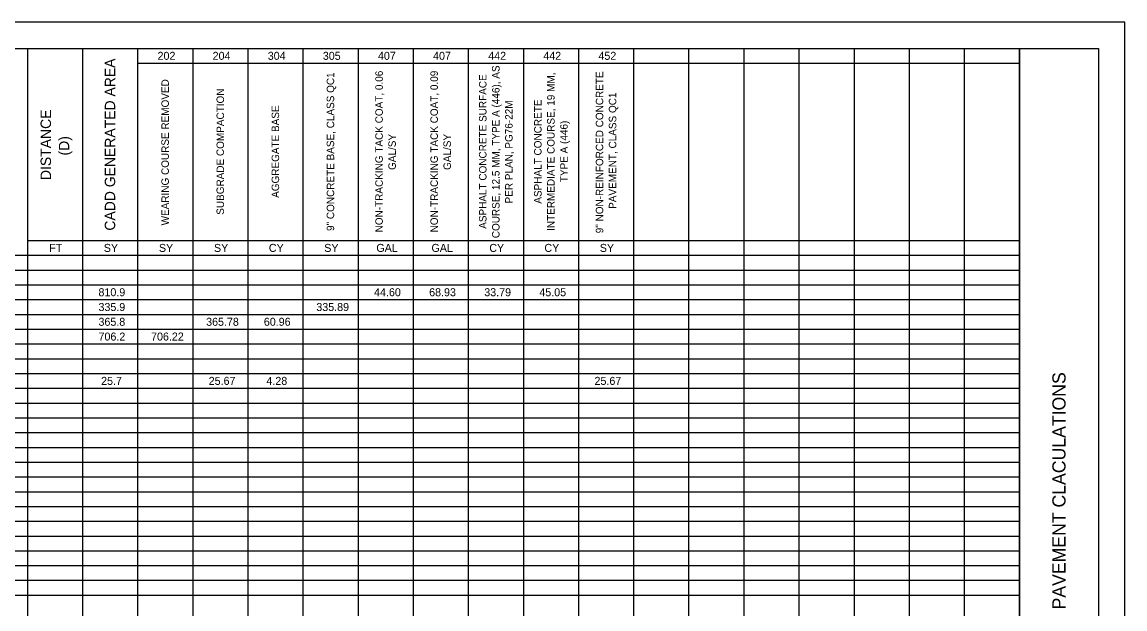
# Model space of a CAD drawing. Extents: x 0 to 34, y 0 to 22.
# Drawn here: x 13.11 to 34, y 10.88 to 22 of the extents above; entities that cross this region are included whole.
import ezdxf

# ---------------------------------------------------------------- set-up
doc = ezdxf.new("R2010")
doc.units = 0
for name, color, linetype in [('SH_Border', 7, 'Continuous'), ('SH_Cut_Line', 7, 'Continuous'), ('SH_Data', 7, 'Continuous'), ('SH_Text', 7, 'Continuous')]:
    doc.layers.add(name, color=color, linetype=linetype)

msp = doc.modelspace()

# ---------------------------------------------------------------- linework, layer by layer
at = {"layer": 'SH_Border'}
msp.add_line((32, 0.5), (32, 21.5), dxfattribs=at)
msp.add_lwpolyline([(1.5, 21.5), (33.5, 21.5), (33.5, 0.5), (1.5, 0.5)], close=True, dxfattribs=at)
at = {"layer": 'SH_Cut_Line'}
msp.add_lwpolyline([(0, 0), (34, 0), (34, 22), (0, 22)], close=True, dxfattribs=at)
at = {"layer": 'SH_Text'}
for p, q in [((1.5, 21.5), (32, 21.5)), ((13.212, 21.5), (13.212, 1.34)), ((14.256, 21.5), (14.256, 1.34)), ((15.299, 21.5), (15.299, 0.5)), ((16.343, 21.5), (16.343, 0.5)), ((17.387, 21.5), (17.387, 0.5)), ((18.431, 21.5), (18.431, 0.5)), ((19.475, 21.5), (19.475, 0.5)), ((20.518, 21.5), (20.518, 0.78)), ((21.562, 21.5), (21.562, 0.5)), ((22.606, 21.5), (22.606, 0.5)), ((23.65, 21.5), (23.65, 0.5)), ((24.694, 21.5), (24.694, 0.5)), ((25.737, 21.5), (25.737, 0.5)), ((26.781, 21.5), (26.781, 0.5)), ((27.825, 21.5), (27.825, 0.5)), ((28.869, 21.5), (28.869, 0.5)), ((29.912, 21.5), (29.912, 0.5)), ((30.956, 21.5), (30.956, 0.5)), ((32, 21.5), (32, 0.5)), ((15.299, 21.22), (32, 21.22)), ((13.212, 17.86), (32, 17.86)), ((1.5, 17.58), (32, 17.58)), ((1.5, 17.3), (32, 17.3)), ((1.5, 17.02), (32, 17.02)), ((1.5, 16.74), (32, 16.74)), ((1.5, 16.46), (32, 16.46)), ((1.5, 16.18), (32, 16.18)), ((1.5, 15.9), (32, 15.9)), ((1.5, 15.62), (32, 15.62)), ((1.5, 15.34), (32, 15.34)), ((1.5, 15.06), (32, 15.06)), ((1.5, 14.78), (32, 14.78)), ((1.5, 14.5), (32, 14.5)), ((1.5, 14.22), (32, 14.22)), ((1.5, 13.94), (32, 13.94)), ((1.5, 13.66), (32, 13.66)), ((1.5, 13.38), (32, 13.38)), ((1.5, 13.1), (32, 13.1)), ((1.5, 12.82), (32, 12.82)), ((1.5, 12.54), (32, 12.54)), ((1.5, 12.26), (32, 12.26)), ((1.5, 11.98), (32, 11.98)), ((1.5, 11.7), (32, 11.7)), ((1.5, 11.42), (32, 11.42)), ((1.5, 11.14), (32, 11.14))]:
    msp.add_line(p, q, dxfattribs=at)

# ---------------------------------------------------------------- texts
at = {"layer": 'SH_Data'}
msp.add_text('PAVEMENT CLACULATIONS', height=0.25, rotation=90, dxfattribs=at).set_placement((32.875, 10.868))
at = {"layer": 'SH_Text'}
for s, height, p in [('CADD GENERATED AREA', 0.19771, (14.876, 18.047)), ('COURSE, 12.5 MM, TYPE A (446), AS ', 0.14122, (22.155, 17.904)), ('WEARING COURSE REMOVED', 0.14122, (15.892, 18.147)), ('9" CONCRETE BASE, CLASS QC1', 0.14122, (19.023, 18.041)), ('NON-TRACKING TACK COAT, 0.06 ', 0.14122, (19.944, 18.014)), ('NON-TRACKING TACK COAT, 0.09 ', 0.14122, (20.987, 18.014)), ('ASPHALT CONCRETE SURFACE ', 0.14122, (21.908, 18.082)), ('INTERMEDIATE COURSE, 19 MM, ', 0.14122, (23.198, 18.042)), ('9" NON-REINFORCED CONCRETE ', 0.14122, (24.119, 17.997)), ('SUBGRADE COMPACTION', 0.14122, (16.936, 18.348)), ('PER PLAN, PG76-22M', 0.14122, (22.402, 18.562)), ('ASPHALT CONCRETE ', 0.14122, (22.951, 18.558)), ('PAVEMENT, CLASS QC1', 0.14122, (24.366, 18.46)), ('DISTANCE ', 0.1977, (13.66, 19.005)), ('AGGREGATE BASE', 0.14122, (17.98, 18.668)), ('TYPE A (446)', 0.14122, (23.446, 18.966)), ('GAL/SY', 0.1412, (20.191, 19.197)), ('GAL/SY', 0.1412, (21.234, 19.197)), ('(D)', 0.1977, (14.006, 19.471))]:
    msp.add_text(s, height=height, rotation=90, dxfattribs=at).set_placement(p)
for s, p in [('202', (15.678, 21.284)), ('204', (16.721, 21.284)), ('304', (17.765, 21.284)), ('305', (18.808, 21.284)), ('407', (19.852, 21.284)), ('407', (20.896, 21.284)), ('442', (21.941, 21.284)), ('442', (22.984, 21.284)), ('452', (24.028, 21.284)), ('FT', (13.627, 17.644)), ('SY', (14.66, 17.644)), ('SY', (15.704, 17.644)), ('SY', (16.747, 17.644)), ('CY', (17.786, 17.644)), ('SY', (18.835, 17.644)), ('GAL', (19.822, 17.644)), ('GAL', (20.866, 17.644)), ('CY', (21.961, 17.644)), ('CY', (23.005, 17.644)), ('SY', (24.054, 17.644)), ('810.9', (14.559, 16.804)), ('44.60', (19.779, 16.804)), ('68.93', (20.822, 16.804)), ('33.79', (21.866, 16.804)), ('45.05', (22.909, 16.804)), ('335.9', (14.559, 16.524)), ('335.89', (18.685, 16.524)), ('365.8', (14.559, 16.244)), ('365.78', (16.598, 16.244)), ('60.96', (17.691, 16.244)), ('706.2', (14.56, 15.964)), ('706.22', (15.555, 15.964)), ('25.7', (14.609, 15.124)), ('25.67', (16.647, 15.124)), ('4.28', (17.74, 15.124)), ('25.67', (23.954, 15.124))]:
    msp.add_text(s, height=0.1515, dxfattribs=at).set_placement(p)

doc.saveas('drawing.dxf')
